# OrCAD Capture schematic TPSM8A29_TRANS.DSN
size D; title: TPSM8A29 2.7-V to 16-V Input, 15-A Buck Power Module with; rev: 1.0; note: Datasheet:SLVSFQ9                EVM:SLVUBX0; note: Synchronous Step Down Converter
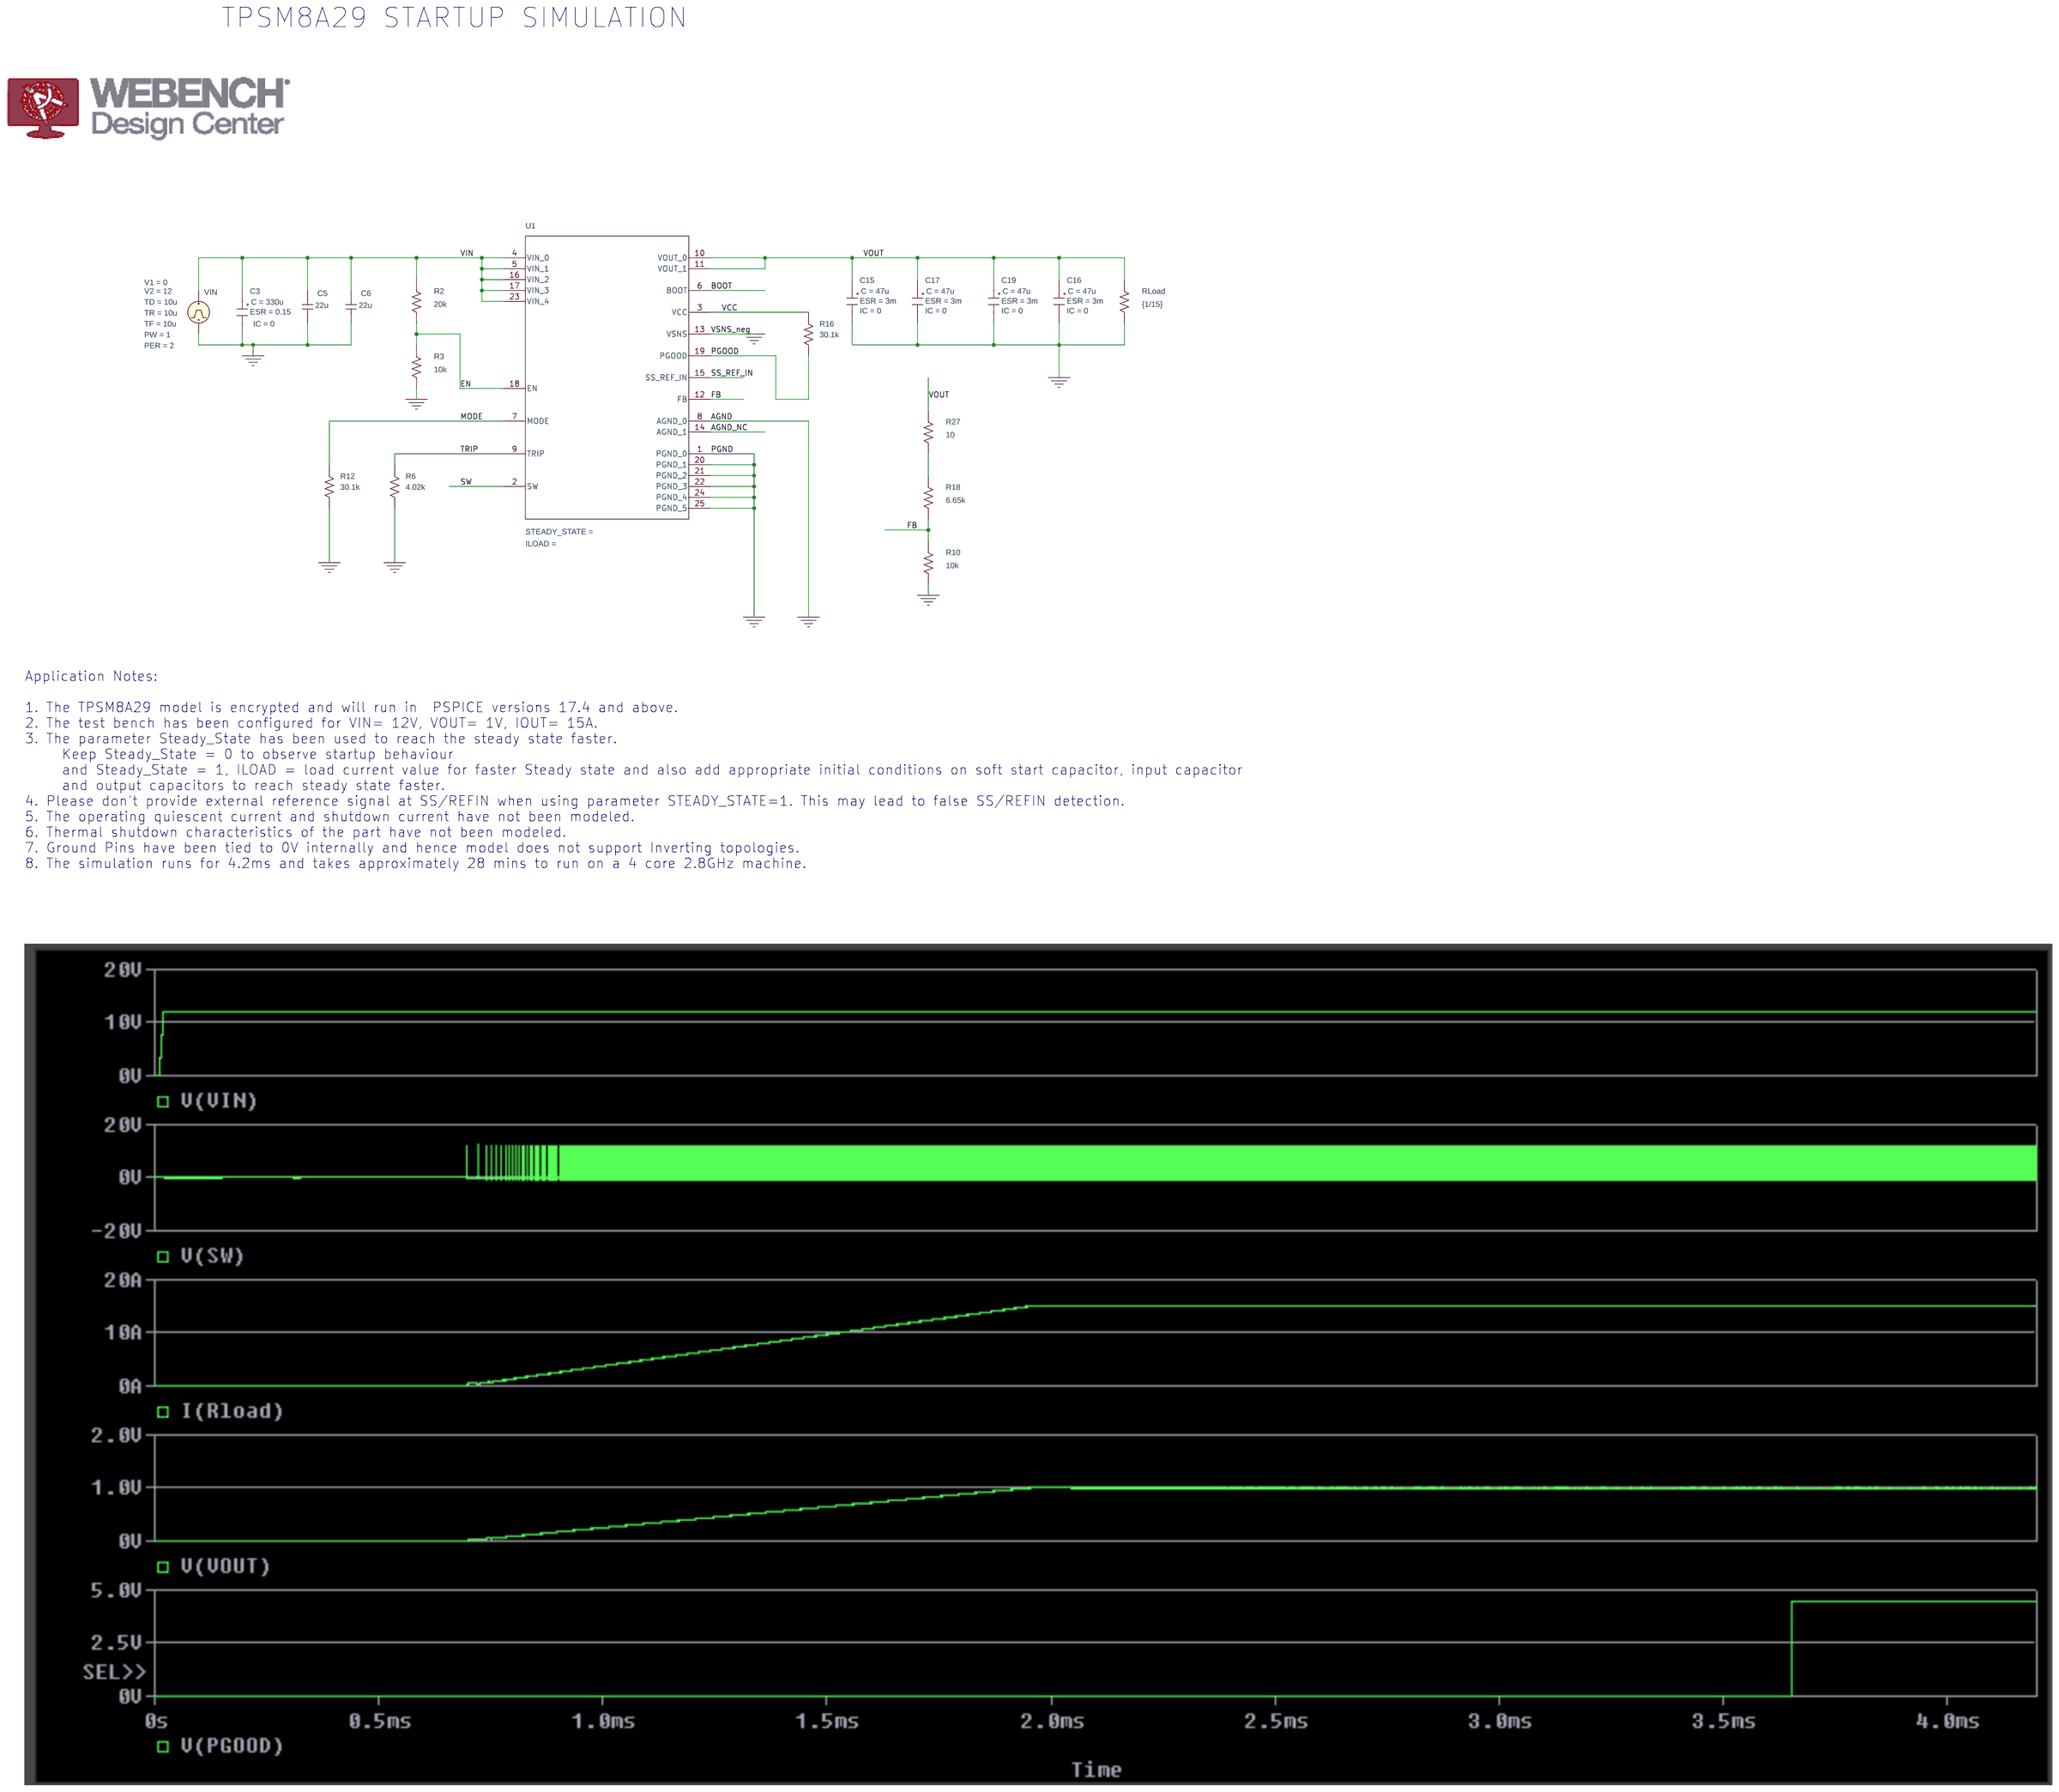
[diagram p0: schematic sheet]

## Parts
C3  CESR
C5  22u  [RAD/CK05]
C6  22u  [RAD/CK05]
C15  CESR
C16  CESR
C17  CESR
C19  CESR
R2  20k  [AX/RC05]
R3  10k  [AX/RC05]
R6  4.02k  [AX/RC05]
R10  10k  [AX/RC05]
R12  30.1k  [AX/RC05]
R16  30.1k  [AX/RC05]
R18  6.65k  [AX/RC05]
R27  10  [AX/RC05]
RLoad  {1/15}  [AX/RC05]
U1  Value  [RDG0025A-MFG]
VIN  VPULSE

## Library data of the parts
C3 = CESR_0: C: 330u; ESR: 0.15; IC: 0; PSpiceTemplate: X^@REFDES %IN %OUT @MODEL PARAMS:  ?C|C=@C||C=100u|  ?ESR|ESR=@ESR||ESR=0.01| ?X|X=@X||X=2|  ?IC|IC=@IC||IC=2|; X: 1
C5 C6 = c_0
C15-C17 C19 = CESR_0: C: 47u; ESR: 3m; IC: 0; PSpiceTemplate: X^@REFDES %IN %OUT @MODEL PARAMS:  ?C|C=@C||C=100u|  ?ESR|ESR=@ESR||ESR=0.01| ?X|X=@X||X=2|  ?IC|IC=@IC||IC=2|; X: 1
R2 R3 R6 R10 R12 R16 R18 R27 RLoad = R
U1 = TPSM8A29RDG_TRANS
VIN = VPULSE: PER: 2; PW: 1; TD: 10u; TF: 10u; TR: 10u; V1: 0; V2: 12

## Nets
AGND_NC: U1.14(AGND_1)
VCC: R16.1 U1.3(VCC)
VIN: C3.1(IN) C5.1 C6.1 R2.1 U1.4(VIN_0) U1.5(VIN_1) U1.16(VIN_2) U1.17(VIN_3) U1.23(VIN_4) VIN.1(+)
0: C3.2(OUT) C5.2 C6.2 C15.2(OUT) C16.2(OUT) C17.2(OUT) C19.2(OUT) R3.2 R6.2 R10.2 R12.2 RLoad.2 U1.1(PGND_0) U1.8(AGND_0) U1.13(VSNS) U1.20(PGND_1) U1.21(PGND_2) U1.22(PGND_3) U1.24(PGND_4) U1.25(PGND_5) VIN.2(-)
BOOT: U1.6(BOOT)
EN: R2.2 R3.1 U1.18(EN)
FB: R10.1 R18.2 U1.12(FB)
MODE: R12.1 U1.7(MODE)
PGOOD: R16.2 U1.19(PGOOD)
SS_REF_IN: U1.15(SS_REF_IN)
SW: U1.2(SW)
TRIP: R6.1 U1.9(TRIP)
VOUT: C15.1(IN) C16.1(IN) C17.1(IN) C19.1(IN) R27.1 RLoad.1 U1.10(VOUT_0) U1.11(VOUT_1)
N16844745: R18.1 R27.2

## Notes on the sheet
- TPSM8A29 STARTUP SIMULATION
- Application Notes:
  1. The TPSM8A29 model is encrypted and will run in  PSPICE versions 17.4 and above.
  2. The test bench has been configured for VIN= 12V, VOUT= 1V, IOUT= 15A.
  3. The parameter Steady_State has been used to reach the steady state faster.
       Keep Steady_State = 0 to observe startup behaviour
       and Steady_State = 1, ILOAD = load current value for faster Steady state and also add appropriate initial conditions on soft start capacitor, input capacitor
       and output capacitors to reach steady state faster.
  4. Please don't provide external reference signal at SS/REFIN when using parameter STEADY_STATE=1. This may lead to false SS/REFIN detection.
  5. The operating quiescent current and shutdown current have not been modeled.
  6. Thermal shutdown characteristics of the part have not been modeled.
  7. Ground Pins have been tied to 0V internally and hence model does not support Inverting topologies.
  8. The simulation runs for 4.2ms and takes approximately 28 mins to run on a 4 core 2.8GHz machine.
